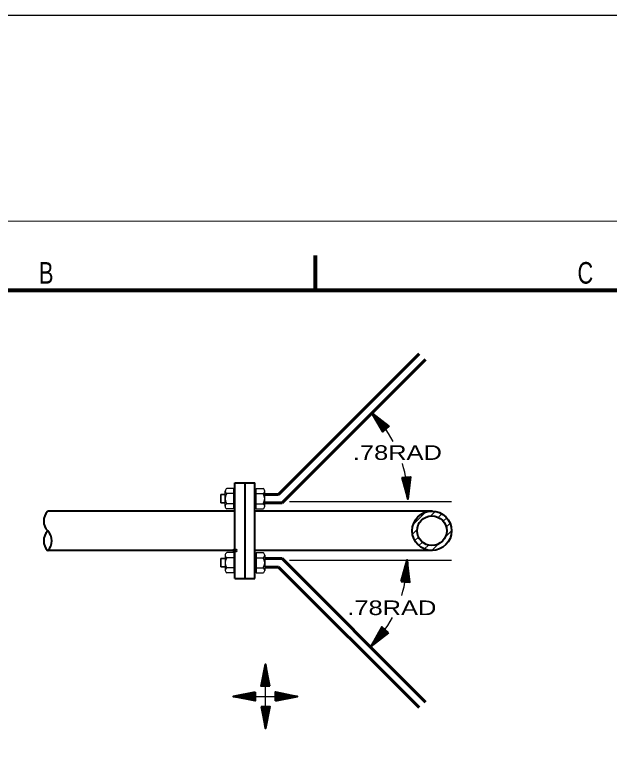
# Model space of a CAD drawing. Extents: x 55 to 190, y 198 to 264.
# Drawn here: x 78.68 to 89.01, y 248.35 to 261.43 of the extents above; entities that cross this region are included whole.
import ezdxf
from ezdxf.enums import TextEntityAlignment as Align

# ---------------------------------------------------------------- set-up
doc = ezdxf.new("R2010")
doc.units = 0
doc.header["$LTSCALE"] = 0.1
doc.header["$PDMODE"] = 32
doc.header["$PDSIZE"] = 0.05
for name, color, linetype, lineweight in [('1', 7, 'Continuous', 25), ('2', 7, 'Continuous', 40), ('3', 7, 'Continuous', 25)]:
    doc.layers.add(name, color=color, linetype=linetype, lineweight=lineweight)

msp = doc.modelspace()

# ---------------------------------------------------------------- linework, layer by layer
at = {"layer": '1', "lineweight": 80}
msp.add_line((83.8915, 257.2525), (83.8915, 256.6525), dxfattribs=at)
at = {"layer": '1', "lineweight": 13}
msp.add_lwpolyline([(62.4915, 257.8525), (146.5927, 257.8525), (146.5927, 198.4512), (62.4915, 198.4512)], close=True, dxfattribs=at)
at = {"layer": '1', "lineweight": 80}
msp.add_lwpolyline([(65.1915, 256.6525), (145.3927, 256.6525), (145.3927, 199.6512), (65.1915, 199.6512)], close=True, dxfattribs=at)
at = {"layer": '2', "lineweight": 60}
for p, q in [((83.2571, 253.1025), (85.7, 255.5454)), ((83.3174, 252.9572), (85.8095, 255.4493)), ((83.0171, 253.1025), (83.2571, 253.1025)), ((83.0171, 252.9572), (83.3174, 252.9572)), ((83.0171, 251.9875), (83.3174, 251.9875)), ((83.3174, 251.9875), (85.8095, 249.4957)), ((83.0171, 251.8425), (83.2571, 251.8425)), ((83.2571, 251.8425), (85.7, 249.3996))]:
    msp.add_line(p, q, dxfattribs=at)
at = {"layer": '2'}
for p, q in [((85.1234, 254.2388), (84.8705, 254.5259)), ((84.8705, 254.5259), (85.1496, 254.2613)), ((84.8705, 254.5259), (85.0808, 254.2018)), ((84.8705, 254.5259), (85.1086, 254.2261)), ((84.8705, 254.5259), (85.1367, 254.2508)), ((84.8705, 254.5259), (85.1655, 254.2759)), ((85.4999, 253.0228), (85.4166, 253.4004)), ((85.4999, 253.0228), (85.4378, 253.4022)), ((85.4999, 253.0228), (85.4547, 253.403)), ((85.4727, 253.4043), (85.4999, 253.0228)), ((85.4999, 253.0228), (85.4917, 253.4057)), ((85.4999, 253.0228), (85.529, 253.4081)), ((82.5009, 251.6422), (82.5009, 253.3027)), ((82.5009, 253.3027), (82.8432, 253.3027)), ((82.6742, 253.3027), (82.6742, 251.6422)), ((82.8432, 251.6422), (82.8432, 253.3027)), ((82.5009, 252.8154), (79.2497, 252.8154)), ((85.9293, 252.8154), (82.8432, 252.8154)), ((82.5009, 252.1296), (79.2497, 252.1296)), ((85.9293, 252.1296), (82.8432, 252.1296)), ((85.4875, 251.9669), (85.4042, 251.5893)), ((85.4875, 251.9669), (85.4253, 251.5875)), ((85.4875, 251.9669), (85.4423, 251.5867)), ((85.4602, 251.5853), (85.4875, 251.9669)), ((85.4875, 251.9669), (85.4793, 251.584)), ((85.4875, 251.9669), (85.5166, 251.5816)), ((82.5009, 251.6422), (82.8432, 251.6422)), ((84.8581, 250.4638), (85.0684, 250.7879)), ((84.8581, 250.4638), (85.0962, 250.7635)), ((85.111, 250.7508), (84.8581, 250.4638)), ((84.8581, 250.4638), (85.1242, 250.7389)), ((84.8581, 250.4638), (85.1372, 250.7284)), ((84.8581, 250.4638), (85.1531, 250.7138)), ((83.0295, 250.1534), (82.9734, 249.7711)), ((83.0295, 250.1534), (83.0107, 249.7711)), ((83.03, 249.7708), (83.0295, 250.1534)), ((83.0295, 250.1534), (83.065, 249.7706)), ((83.0295, 250.1534), (83.0478, 249.7711)), ((83.0295, 250.1534), (83.0864, 249.7711)), ((82.471, 249.5946), (82.8533, 249.6515)), ((82.471, 249.5946), (82.8538, 249.6301)), ((82.471, 249.5946), (82.8533, 249.6129)), ((82.8536, 249.5951), (82.471, 249.5946)), ((82.471, 249.5946), (82.8533, 249.5385)), ((82.471, 249.5946), (82.8533, 249.5758)), ((83.5883, 249.5946), (83.2055, 249.5592)), ((83.2057, 249.5941), (83.5883, 249.5946)), ((83.5883, 249.5946), (83.206, 249.6507)), ((83.5883, 249.5946), (83.206, 249.6134)), ((83.5883, 249.5946), (83.206, 249.5764)), ((83.5883, 249.5946), (83.206, 249.5377)), ((83.0295, 249.0361), (82.9726, 249.4184)), ((83.0295, 249.0361), (82.9941, 249.4189)), ((83.0295, 249.0361), (83.0113, 249.4184)), ((83.029, 249.4187), (83.0295, 249.0361)), ((83.0295, 249.0361), (83.0856, 249.4184)), ((83.0295, 249.0361), (83.0483, 249.4184))]:
    msp.add_line(p, q, dxfattribs=at)
at = {"layer": '2', "lineweight": 35}
for p, q in [((82.331, 253.1025), (82.2561, 253.1025)), ((82.2561, 253.1025), (82.2561, 252.9572)), ((82.331, 252.9572), (82.2561, 252.9572)), ((82.3289, 251.988), (82.2546, 251.988)), ((82.2546, 251.988), (82.2546, 251.8428)), ((82.3289, 251.8428), (82.2546, 251.8428))]:
    msp.add_line(p, q, dxfattribs=at)
at = {"layer": '2', "lineweight": 25}
for p, q in [((82.3313, 252.8974), (82.3313, 253.162)), ((82.4813, 253.1183), (82.3583, 253.1183)), ((82.4813, 253.2062), (82.3591, 253.2062)), ((82.4813, 252.8527), (82.4813, 253.2062)), ((82.8668, 252.8527), (82.8668, 253.2062)), ((82.8668, 253.2062), (82.9888, 253.2062)), ((82.8668, 253.1183), (82.9898, 253.1183)), ((83.0168, 252.8974), (83.0168, 253.162)), ((83.4454, 252.9815), (86.2577, 252.9815)), ((82.4813, 252.9403), (82.3583, 252.9403)), ((82.4813, 252.8527), (82.3583, 252.8527)), ((82.8668, 252.9403), (82.9898, 252.9403)), ((82.8668, 252.8527), (82.9898, 252.8527)), ((82.3313, 252.0476), (82.3313, 251.7827)), ((82.4813, 252.0923), (82.3583, 252.0923)), ((82.4813, 252.0923), (82.4813, 251.7385)), ((82.8668, 252.0923), (82.8668, 251.7385)), ((82.8668, 252.0923), (82.9898, 252.0923)), ((83.0168, 252.0476), (83.0168, 251.7827)), ((82.4813, 252.0042), (82.3583, 252.0042)), ((82.8668, 252.0042), (82.9898, 252.0042)), ((83.4454, 251.9632), (86.2577, 251.9632)), ((82.4813, 251.8269), (82.3583, 251.8269)), ((82.8668, 251.8269), (82.9898, 251.8269)), ((82.4813, 251.7385), (82.3591, 251.7385)), ((82.8668, 251.7385), (82.9888, 251.7385)), ((83.0295, 249.0361), (83.0295, 250.1534)), ((82.471, 249.5946), (83.5883, 249.5946))]:
    msp.add_line(p, q, dxfattribs=at)
at = {"layer": '2', "lineweight": 13}
for p, q in [((85.5941, 252.5812), (85.8108, 252.7974)), ((85.8971, 252.7286), (85.978, 252.8096)), ((86.0288, 252.7053), (86.0915, 252.7686)), ((86.1164, 252.6376), (86.1767, 252.6976)), ((86.1685, 252.5347), (86.2357, 252.6019)), ((85.5819, 252.4137), (85.6634, 252.4952)), ((86.1505, 252.3611), (86.2609, 252.4717)), ((85.6235, 252.3002), (85.6865, 252.3635)), ((85.6936, 252.2153), (85.7547, 252.2756)), ((85.7904, 252.1563), (85.8576, 252.2232)), ((85.9198, 252.1309), (86.0307, 252.2418))]:
    msp.add_line(p, q, dxfattribs=at)
at = {"layer": '2'}
for points in [[(85.18, 254.2886), (85.0647, 254.188), (84.8705, 254.5259)], [(85.18, 254.2886), (84.8705, 254.5259), (85.0949, 254.2134)], [(85.397, 253.3988), (85.5499, 253.4096), (85.4999, 253.0228)], [(85.397, 253.3988), (85.4999, 253.0228), (85.5108, 253.4073)], [(85.3846, 251.5909), (85.5375, 251.58), (85.4875, 251.9669)], [(85.3846, 251.5909), (85.4875, 251.9669), (85.4983, 251.5824)], [(85.1676, 250.7011), (85.0523, 250.8016), (84.8581, 250.4638)], [(85.1676, 250.7011), (84.8581, 250.4638), (85.0824, 250.7762)], [(83.1057, 249.7711), (82.9528, 249.7714), (83.0295, 250.1534)], [(83.1057, 249.7711), (83.0295, 250.1534), (82.9919, 249.7708)], [(82.8533, 249.6708), (82.853, 249.5179), (82.471, 249.5946)], [(82.8533, 249.6708), (82.471, 249.5946), (82.8536, 249.557)], [(83.206, 249.5184), (83.5883, 249.5946), (83.2057, 249.6322)], [(83.206, 249.5184), (83.2063, 249.6713), (83.5883, 249.5946)], [(82.9533, 249.4184), (83.0295, 249.0361), (83.0671, 249.4187)], [(82.9533, 249.4184), (83.1062, 249.4181), (83.0295, 249.0361)]]:
    msp.add_lwpolyline(points, dxfattribs=at)
for centre, radius in [((85.9189, 252.473), 0.3424), ((85.919, 252.473), 0.2571)]:
    msp.add_circle(centre, radius, dxfattribs=at)
at = {"layer": '2', "lineweight": 25}
for centre, radius, start, end in [((83.3903, 253.0229), 2.1095, 28.38076, 45.43875), ((83.3903, 253.0229), 2.1095, 0, 17.02996), ((82.4948, 253.0293), 0.1633, 147.00616, 212.94297), ((82.3812, 253.1619), 0.0494, 116.78269, 241.8391), ((82.9668, 253.1619), 0.0494, 298.1609, 63.21731), ((82.8532, 253.0293), 0.1633, 327.05703, 32.99384), ((82.3808, 252.8967), 0.0494, 117.8877, 242.03419), ((82.9672, 252.8967), 0.0494, 297.96581, 62.1123), ((82.3808, 252.0482), 0.0494, 117.96581, 242.1123), ((82.9672, 252.0482), 0.0494, 297.8877, 62.03419), ((82.4948, 251.9157), 0.1633, 147.05703, 212.99384), ((82.8532, 251.9157), 0.1633, 327.00616, 32.94297), ((83.3779, 251.9667), 2.1095, 342.97004, 0), ((82.3812, 251.7831), 0.0494, 118.1609, 243.21731), ((82.9668, 251.7831), 0.0494, 296.78269, 61.8391), ((83.3779, 251.9667), 2.1095, 314.56125, 331.61924)]:
    msp.add_arc(centre, radius, start, end, dxfattribs=at)
at = {"layer": '2'}
for centre, start, end in [((79.4273, 252.6398), 135.97881, 224.0225), ((79.4273, 252.2967), 135.9775, 224.02119), ((79.0723, 252.2967), 315.97881, 44.0225)]:
    msp.add_arc(centre, 0.2469, start, end, dxfattribs=at)
msp.add_point((82.5009, 252.1296), dxfattribs=at)
at = {"layer": '3'}
msp.add_line((62.4915, 261.4312), (146.5927, 261.4312), dxfattribs=at)

# ---------------------------------------------------------------- texts
at = {"layer": '1', "width": 0.75}
for s, p in [('C', (88.5831, 256.765)), ('B', (79.2242, 256.765))]:
    msp.add_text(s, height=0.375, dxfattribs=at).set_placement(p, align=Align.CENTER)
at = {"layer": '2', "width": 1.3}
for p in [(85.3199, 253.7037), (85.2243, 251.007)]:
    msp.add_text('.78RAD', height=0.254, dxfattribs=at).set_placement(p, align=Align.CENTER)

doc.saveas('drawing.dxf')
